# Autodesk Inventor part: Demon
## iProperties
Shininess: 64.0
Length Units: 11269
Angle Units: 11279
Time Units: 11290
Mass Units: 11283
Length Display Precision: 3
Angle Display Precision: 2
Compacted: True
Part Number: Demon
Document SubType Name: Modeling
Created: 2005-04
Material: Steel, Mild
Designer: John Blackburn
Manufacturer: Standard
Standards Organization: Custom
Density: 0.0
Volumn: 0.0
Area: 0.0
PropertySet Name: Model Information
Control State: 0
Master: False
Checked Out: False
Author: John Blackburn
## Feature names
1. Extrusion1
2. Extrusion2
3. Extrusion3
